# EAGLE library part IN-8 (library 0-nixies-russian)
IN-8: medium numeric frontview nixie tube
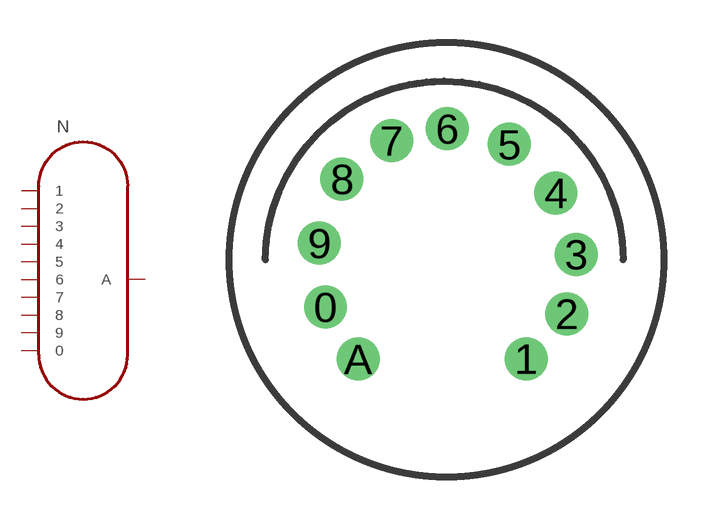
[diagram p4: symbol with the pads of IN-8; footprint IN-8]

Designator prefix N

## IN-8  [IN-8]
0  0
1  1
2  2
3  3
4  4
5  5
6  6
7  7
8  8
9  9
A  A

## Footprint IN-8 (pad centres in mm)
May be used with socket: 11-pin- Russian
drill 1 round: 0 -4.244,-1.655; 1 2.792,-3.483; 2 4.222,-1.907; 3 4.556,0.189; 4 3.837,2.348; 5 2.203,4.052; 6 0.034,4.603; 7 -1.928,4.186; 8 -3.666,2.83; 9 -4.461,0.584; A -3.101,-3.49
